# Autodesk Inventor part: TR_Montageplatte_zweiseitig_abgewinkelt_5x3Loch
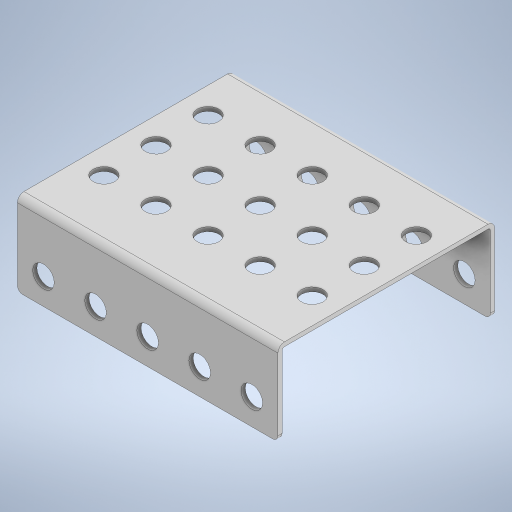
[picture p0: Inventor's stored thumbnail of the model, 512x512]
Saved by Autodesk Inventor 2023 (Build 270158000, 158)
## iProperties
Created: 2023-11
Part Number: TR_Montageplatte_zweiseitig_abgewinkelt_5x3Loch
Material: Generisch
Document SubType Name: Modeling
Designer: Greiner
Density: 1 g/cm^3
Appearance: Vorgabe
Author: Greiner
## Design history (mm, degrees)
sketch "Skizze1"
  geometry: L1 (0, 20)-(14.75, 20); L2 (15.2, 19.55)-(15.2, -19.55); L3 (14.75, -20)-(0, -20); L4 (0, -20)-(0, -20.8); L5 (0, -20.8)-(14.75, -20.8); L6 (16, -19.55)-(16, 19.55); L7 (14.75, 20.8)-(0, 20.8); L8 (0, 20.8)-(0, 20); A1 r 0.45 centre (14.75, 19.55) between (15.2, 19.55) and (14.75, 20); A2 r 0.45 centre (14.75, -19.55) between (14.75, -20) and (15.2, -19.55); A3 r 1.25 centre (14.75, 19.55) between (16, 19.55) and (14.75, 20.8); A4 r 1.25 centre (14.75, -19.55) between (14.75, -20.8) and (16, -19.55); 2 further points
  constraints: 16 end point, 8 point on circle, 8 tangent, 5 perpendicular, 4 centre point, 2 coincident, 2 equal radius, 2 point on line, 1 horizontal, 1 horizontal alignment, 1 midpoint, 1 vertical alignment
  dimensions: "d3" = 40 distance between parallel lines of L3 L1 (= Lochy + Einheitsmaß); "d4" = 0.8 distance between parallel lines of L1 L7; "d5" = 1.25 radius of A3; "d6" = 16 distance from line of L7.end L6
extrude "Extrusion1" new body sketch "Skizze1" stored distance "d7" = 50 (computed from Lochx, Einheitsmaß); taper "d8" = 0 deg
sketch "Skizze2"
  geometry: L1 (0, 0)-(50, 0) reference; L2 (50, 14.75)-(50, 0) reference; C1 r 2.075 at (45, 5); 3 further points
  constraints: 2 midpoint, 1 centre point
  dimensions: "d9" = 4.15 diameter of C1 (= 2 x Radius); "d10" = 5 vertical distance of point (25, 0) C1.centre (= 0.5 x Einheitsmaß); "d19" = 5 distance from line of C1.centre L2 (= 0.5 x Einheitsmaß)
extrude "Extrusion2" cut sketch "Skizze2" extent not by distance; stored distance "d11" = 0; taper "d12" = 0 deg
pattern_linear "Rechteckige Anordnung2" dims "d22" = 10 (= Einheitsmaß)
sketch "Skizze3"
  geometry: L1 (50, 39.1)-(50, 0) reference; L2 (0, 40.35)-(50, 40.35) reference; C1 r 2.075 at (45, 30.35); 1 further point
  constraints: 1 centre point
  dimensions: "d16" = 4.15 diameter of C1 (= 2 x Radius); "d17" = 5 distance from line of C1.centre L1 (= 0.5 x Einheitsmaß); "d18" = 10 distance from line of L2 C1.centre (= Einheitsmaß)
extrude "Extrusion3" cut sketch "Skizze3" extent not by distance; stored distance "d23" = 0; taper "d24" = 0 deg
pattern_linear "Rechteckige Anordnung3" dims "d27" = 10 (= Einheitsmaß), "d30" = 10 (= Einheitsmaß)
fillet "Rundung1" dims "d31" = 1
node "Volumenkörper1"
other parameters: "Einheitsmaß" = 10 [user parameter; used in 9 equation terms], "Radius" = 2.075 [user parameter; used in 2 equation terms], "Fasen" = 0.5 [user parameter], "Dicke" = 0.8 [user parameter], "Breitloch" = 2 [user parameter], "Langloch" = 32 [user parameter], "AchteckUmkreis" = 6 [user parameter], "DAchsAufnahme" = 4.1 [user parameter], "AchsDurchmesser" = 4 [user parameter], "AchsFase" = 0.5 [user parameter], "Lochy" = 30 [user parameter; used in 2 equation terms]
